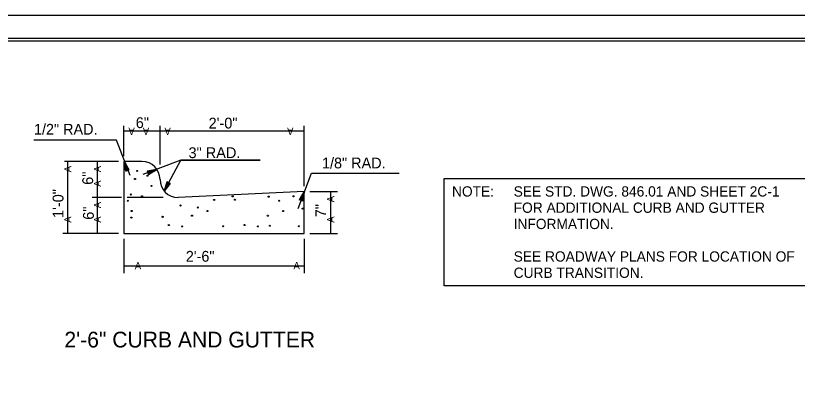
# Model space of a CAD drawing. Extents: x 1252282 to 1252460, y 733735 to 733845.
# Drawn here: x 1252344.6 to 1252421, y 733807 to 733844.5 of the extents above; entities that cross this region are included whole.
import ezdxf

# ---------------------------------------------------------------- set-up
doc = ezdxf.new("R2010")
doc.units = 0
for name, color, linetype in [('Default', 7, 'Continuous'), ('Old_Level_2', 7, 'Continuous'), ('Old_Level_23', 7, 'Continuous'), ('Old_Level_3', 7, 'Continuous'), ('Sheet Cutting Line CELL', 7, 'Continuous'), ('Sheet Plot Border Inside CELL', 7, 'Continuous'), ('Sheet Plot Border Outside CELL', 7, 'Continuous'), ('Sheet Typical CELL', 7, 'Continuous')]:
    doc.layers.add(name, color=color, linetype=linetype)

msp = doc.modelspace()

# ---------------------------------------------------------------- linework, layer by layer
at = {"layer": 'Default'}
msp.add_lwpolyline([(1252386.483, 733828.578), (1252426.564, 733828.578), (1252426.564, 733818.059), (1252386.483, 733818.059)], close=True, dxfattribs=at)
at = {"layer": 'Old_Level_2'}
for p, q in [((1252355.159, 733830.231), (1252355.653, 733829.406)), ((1252355.159, 733830.231), (1252355.34, 733829.287)), ((1252355.34, 733829.287), (1252355.653, 733829.406)), ((1252358.387, 733829.459), (1252357.448, 733829.278)), ((1252357.448, 733829.278), (1252357.567, 733828.961)), ((1252358.387, 733829.459), (1252357.567, 733828.961)), ((1252359.097, 733827.312), (1252359.397, 733828.22)), ((1252359.097, 733827.312), (1252359.688, 733828.061)), ((1252359.688, 733828.061), (1252359.397, 733828.22)), ((1252372.802, 733827.289), (1252372.317, 733826.474)), ((1252372.802, 733827.289), (1252372.621, 733826.346)), ((1252372.621, 733826.346), (1252372.317, 733826.474))]:
    msp.add_line(p, q, dxfattribs=at)
for points in [[(1252355.499, 733829.362), (1252355.172, 733830.2), (1252355.424, 733829.322), (1252355.172, 733830.209), (1252355.587, 733829.384), (1252355.177, 733830.2), (1252355.543, 733829.375), (1252355.177, 733830.2), (1252355.463, 733829.34), (1252355.177, 733830.2), (1252355.375, 733829.309), (1252355.177, 733830.2), (1252355.362, 733829.3), (1252355.177, 733830.2), (1252355.477, 733829.34), (1252355.177, 733830.178), (1252355.622, 733829.393), (1252355.181, 733830.187), (1252355.569, 733829.375), (1252355.208, 733830.125), (1252355.53, 733829.362), (1252355.181, 733830.187), (1252355.521, 733829.362), (1252355.181, 733830.178), (1252355.411, 733829.322), (1252355.186, 733830.169), (1252355.437, 733829.331), (1252355.181, 733830.169), (1252355.605, 733829.393), (1252355.177, 733830.187), (1252355.649, 733829.406), (1252355.181, 733830.169), (1252355.649, 733829.406), (1252355.186, 733830.187), (1252355.331, 733829.957), (1252355.203, 733830.169), (1252355.596, 733829.384), (1252355.181, 733830.169), (1252355.349, 733829.3), (1252355.181, 733830.147), (1252355.344, 733829.3), (1252355.172, 733830.209), (1252355.393, 733829.309), (1252355.203, 733830.156), (1252355.472, 733829.34), (1252355.186, 733830.169), (1252355.455, 733829.34), (1252355.203, 733830.147), (1252355.556, 733829.375), (1252355.181, 733830.187), (1252355.631, 733829.406), (1252355.181, 733830.187), (1252355.371, 733829.3), (1252355.181, 733830.187), (1252355.415, 733829.309), (1252355.181, 733830.169), (1252355.494, 733829.353), (1252355.181, 733830.169), (1252355.525, 733829.362), (1252355.181, 733830.178), (1252355.552, 733829.375), (1252355.181, 733830.178), (1252355.583, 733829.384), (1252355.177, 733830.187), (1252355.613, 733829.406), (1252355.181, 733830.187), (1252355.6, 733829.384), (1252355.181, 733830.187), (1252355.627, 733829.406), (1252355.181, 733830.178), (1252355.468, 733829.34), (1252355.177, 733830.2), (1252355.503, 733829.362), (1252355.177, 733830.2), (1252355.441, 733829.34), (1252355.177, 733830.187), (1252355.428, 733829.322), (1252355.181, 733830.169), (1252355.397, 733829.309), (1252355.177, 733830.187), (1252355.371, 733829.3), (1252355.212, 733830.028), (1252355.362, 733829.3), (1252355.265, 733829.807), (1252355.349, 733829.3), (1252355.296, 733829.746), (1252355.424, 733829.322), (1252355.309, 733829.701), (1252355.534, 733829.362), (1252355.283, 733829.944), (1252355.552, 733829.375), (1252355.305, 733829.869), (1252355.543, 733829.362), (1252355.336, 733829.785), (1252355.499, 733829.353), (1252355.349, 733829.71), (1252355.49, 733829.353), (1252355.283, 733829.975), (1252355.583, 733829.375), (1252355.344, 733829.851), (1252355.583, 733829.384)], [(1252357.518, 733829.111), (1252358.365, 733829.446), (1252357.487, 733829.194), (1252358.378, 733829.446), (1252357.554, 733829.022), (1252358.356, 733829.437), (1252357.532, 733829.075), (1252358.365, 733829.437), (1252357.505, 733829.15), (1252358.365, 733829.437), (1252357.465, 733829.234), (1252358.365, 733829.437), (1252357.461, 733829.247), (1252358.365, 733829.437), (1252357.505, 733829.141), (1252358.334, 733829.437), (1252357.558, 733828.983), (1252358.347, 733829.428), (1252357.54, 733829.044), (1252358.281, 733829.406), (1252357.527, 733829.089), (1252358.347, 733829.428), (1252357.518, 733829.097), (1252358.334, 733829.428), (1252357.487, 733829.203), (1252358.325, 733829.428), (1252357.492, 733829.172), (1252358.325, 733829.428), (1252357.558, 733829.014), (1252358.352, 733829.437), (1252357.567, 733828.969), (1252358.33, 733829.428), (1252357.567, 733828.969), (1252358.347, 733829.428), (1252358.122, 733829.287), (1252358.325, 733829.415), (1252357.554, 733829.022), (1252358.325, 733829.428), (1252357.461, 733829.269), (1252358.312, 733829.428), (1252357.457, 733829.269), (1252358.378, 733829.446), (1252357.479, 733829.225), (1252358.321, 733829.415), (1252357.505, 733829.141), (1252358.325, 733829.428), (1252357.501, 733829.164), (1252358.312, 733829.415), (1252357.54, 733829.058), (1252358.352, 733829.428), (1252357.567, 733828.983), (1252358.352, 733829.428), (1252357.461, 733829.234), (1252358.347, 733829.428), (1252357.479, 733829.203), (1252358.325, 733829.428), (1252357.509, 733829.119), (1252358.33, 733829.428), (1252357.527, 733829.089), (1252358.334, 733829.428), (1252357.54, 733829.058), (1252358.334, 733829.428), (1252357.554, 733829.036), (1252358.347, 733829.437), (1252357.562, 733829.005), (1252358.347, 733829.428), (1252357.554, 733829.014), (1252358.352, 733829.428), (1252357.562, 733828.983), (1252358.334, 733829.428), (1252357.505, 733829.15), (1252358.365, 733829.437), (1252357.518, 733829.111), (1252358.356, 733829.437), (1252357.501, 733829.172), (1252358.352, 733829.437), (1252357.487, 733829.181), (1252358.33, 733829.428), (1252357.479, 733829.216), (1252358.352, 733829.437), (1252357.461, 733829.234), (1252358.193, 733829.406), (1252357.457, 733829.256), (1252357.964, 733829.353), (1252357.457, 733829.269), (1252357.906, 733829.322), (1252357.487, 733829.194), (1252357.871, 733829.3), (1252357.532, 733829.075), (1252358.1, 733829.331), (1252357.532, 733829.058), (1252358.03, 733829.309), (1252357.527, 733829.075), (1252357.95, 733829.278), (1252357.509, 733829.111), (1252357.875, 733829.269), (1252357.509, 733829.128), (1252358.136, 733829.331), (1252357.54, 733829.036), (1252358.012, 733829.269), (1252357.554, 733829.022)], [(1252359.538, 733828.136), (1252359.106, 733827.329), (1252359.604, 733828.105), (1252359.106, 733827.329), (1252359.463, 733828.189), (1252359.115, 733827.342), (1252359.494, 733828.158), (1252359.106, 733827.329), (1252359.573, 733828.123), (1252359.115, 733827.329), (1252359.653, 733828.083), (1252359.106, 733827.329), (1252359.661, 733828.07), (1252359.106, 733827.342), (1252359.556, 733828.136), (1252359.119, 733827.364), (1252359.423, 733828.198), (1252359.119, 733827.364), (1252359.472, 733828.176), (1252359.154, 733827.417), (1252359.511, 733828.158), (1252359.119, 733827.364), (1252359.525, 733828.145), (1252359.128, 733827.364), (1252359.622, 733828.092), (1252359.128, 733827.373), (1252359.595, 733828.114), (1252359.141, 733827.373), (1252359.436, 733828.198), (1252359.119, 733827.351), (1252359.406, 733828.211), (1252359.128, 733827.373), (1252359.406, 733828.22), (1252359.115, 733827.364), (1252359.203, 733827.616), (1252359.128, 733827.382), (1252359.459, 733828.189), (1252359.141, 733827.373), (1252359.679, 733828.061), (1252359.145, 733827.373), (1252359.679, 733828.061), (1252359.106, 733827.329), (1252359.635, 733828.083), (1252359.141, 733827.382), (1252359.556, 733828.123), (1252359.141, 733827.373), (1252359.582, 733828.123), (1252359.141, 733827.395), (1252359.476, 733828.167), (1252359.115, 733827.351), (1252359.41, 733828.211), (1252359.115, 733827.351), (1252359.657, 733828.07), (1252359.119, 733827.364), (1252359.622, 733828.092), (1252359.128, 733827.373), (1252359.542, 733828.136), (1252359.128, 733827.373), (1252359.52, 733828.158), (1252359.128, 733827.364), (1252359.489, 733828.167), (1252359.128, 733827.364), (1252359.467, 733828.176), (1252359.128, 733827.351), (1252359.432, 733828.198), (1252359.119, 733827.364), (1252359.445, 733828.198), (1252359.115, 733827.351), (1252359.414, 733828.211), (1252359.128, 733827.364), (1252359.564, 733828.123), (1252359.106, 733827.329), (1252359.529, 733828.136), (1252359.115, 733827.342), (1252359.591, 733828.114), (1252359.115, 733827.342), (1252359.6, 733828.114), (1252359.128, 733827.373), (1252359.635, 733828.092), (1252359.119, 733827.351), (1252359.661, 733828.07), (1252359.212, 733827.488), (1252359.67, 733828.07), (1252359.353, 733827.669), (1252359.679, 733828.07), (1252359.37, 733827.735), (1252359.617, 733828.092), (1252359.397, 733827.775), (1252359.498, 733828.158), (1252359.234, 733827.585), (1252359.489, 733828.167), (1252359.282, 733827.66), (1252359.498, 733828.158), (1252359.317, 733827.735), (1252359.538, 733828.136), (1252359.366, 733827.797), (1252359.551, 733828.136), (1252359.212, 733827.563), (1252359.467, 733828.189), (1252359.264, 733827.691), (1252359.463, 733828.189)], [(1252372.462, 733826.421), (1252372.797, 733827.267), (1252372.542, 733826.377), (1252372.797, 733827.267), (1252372.378, 733826.443), (1252372.793, 733827.259), (1252372.422, 733826.43), (1252372.793, 733827.267), (1252372.506, 733826.399), (1252372.793, 733827.267), (1252372.586, 733826.368), (1252372.793, 733827.267), (1252372.608, 733826.359), (1252372.793, 733827.267), (1252372.484, 733826.412), (1252372.793, 733827.237), (1252372.348, 733826.452), (1252372.78, 733827.245), (1252372.396, 733826.443), (1252372.758, 733827.184), (1252372.431, 733826.421), (1252372.78, 733827.245), (1252372.449, 733826.421), (1252372.78, 733827.237), (1252372.555, 733826.377), (1252372.775, 733827.223), (1252372.528, 733826.39), (1252372.78, 733827.223), (1252372.356, 733826.452), (1252372.793, 733827.245), (1252372.321, 733826.474), (1252372.78, 733827.237), (1252372.321, 733826.474), (1252372.775, 733827.245), (1252372.639, 733827.012), (1252372.766, 733827.223), (1252372.37, 733826.443), (1252372.78, 733827.223), (1252372.612, 733826.359), (1252372.78, 733827.206), (1252372.616, 733826.359), (1252372.797, 733827.267), (1252372.572, 733826.377), (1252372.766, 733827.214), (1252372.489, 733826.412), (1252372.775, 733827.223), (1252372.511, 733826.399), (1252372.766, 733827.206), (1252372.409, 733826.443), (1252372.78, 733827.245), (1252372.33, 733826.474), (1252372.78, 733827.245), (1252372.59, 733826.359), (1252372.78, 733827.245), (1252372.546, 733826.377), (1252372.78, 733827.223), (1252372.475, 733826.412), (1252372.78, 733827.237), (1252372.44, 733826.421), (1252372.78, 733827.237), (1252372.414, 733826.43), (1252372.78, 733827.237), (1252372.383, 733826.443), (1252372.793, 733827.245), (1252372.352, 733826.465), (1252372.78, 733827.245), (1252372.361, 733826.443), (1252372.78, 733827.245), (1252372.334, 733826.465), (1252372.78, 733827.237), (1252372.493, 733826.412), (1252372.793, 733827.267), (1252372.458, 733826.421), (1252372.793, 733827.259), (1252372.519, 733826.399), (1252372.793, 733827.245), (1252372.537, 733826.377), (1252372.78, 733827.237), (1252372.568, 733826.377), (1252372.793, 733827.245), (1252372.59, 733826.359), (1252372.749, 733827.087), (1252372.608, 733826.359), (1252372.7, 733826.866), (1252372.612, 733826.359), (1252372.669, 733826.8), (1252372.542, 733826.377), (1252372.652, 733826.76), (1252372.427, 733826.421), (1252372.678, 733827.003), (1252372.414, 733826.43), (1252372.665, 733826.928), (1252372.422, 733826.421), (1252372.634, 733826.853), (1252372.462, 733826.412), (1252372.612, 733826.769), (1252372.48, 733826.412), (1252372.678, 733827.034), (1252372.383, 733826.443), (1252372.616, 733826.919), (1252372.383, 733826.443)]]:
    msp.add_lwpolyline(points, dxfattribs=at)
at = {"layer": 'Old_Level_23'}
for p, q in [((1252355.159, 733830.76), (1252355.159, 733833.714)), ((1252358.696, 733833.185), (1252355.159, 733833.185)), ((1252358.696, 733829.922), (1252358.696, 733833.714)), ((1252372.802, 733833.185), (1252358.696, 733833.185)), ((1252372.802, 733827.819), (1252372.802, 733833.714)), ((1252354.634, 733830.231), (1252349.361, 733830.231)), ((1252349.678, 733823.171), (1252349.678, 733830.231)), ((1252352.588, 733826.694), (1252352.588, 733830.231)), ((1252373.331, 733827.289), (1252376.065, 733827.289)), ((1252375.386, 733823.171), (1252375.386, 733827.289)), ((1252354.921, 733826.694), (1252352.055, 733826.694)), ((1252352.588, 733823.171), (1252352.588, 733826.694)), ((1252359, 733826.694), (1252355.472, 733826.694)), ((1252354.634, 733823.171), (1252349.198, 733823.171)), ((1252373.331, 733823.171), (1252376.065, 733823.171)), ((1252355.159, 733822.642), (1252355.159, 733819.308)), ((1252372.802, 733822.642), (1252372.802, 733819.308)), ((1252355.159, 733820.027), (1252372.802, 733820.027))]:
    msp.add_line(p, q, dxfattribs=at)
for points in [[(1252355.755, 733828.855), (1252354.44, 733832.316), (1252346.345, 733832.316)], [(1252359.097, 733827.312), (1252360.733, 733830.345), (1252368.489, 733830.345), (1252360.733, 733830.345), (1252357.011, 733828.939)], [(1252372.189, 733825.627), (1252373.498, 733829.089), (1252382.093, 733829.089)]]:
    msp.add_lwpolyline(points, dxfattribs=at)
at = {"layer": 'Old_Level_3'}
msp.add_lwpolyline([(1252356.927, 733830.231), (1252355.159, 733830.231), (1252355.159, 733823.171), (1252372.802, 733823.171), (1252372.802, 733827.289), (1252360.451, 733826.694)], dxfattribs=at)
for centre, radius in [((1252356.458, 733829.302), 0.0517), ((1252356.246, 733828.514), 0.0517), ((1252357.463, 733828.839), 0.0517), ((1252357.847, 733827.836), 0.0517), ((1252355.839, 733826.995), 0.0517), ((1252355.532, 733826.384), 0.0517), ((1252356.925, 733826.822), 0.0548), ((1252363.988, 733826.458), 0.0517), ((1252365.797, 733826.804), 0.0517), ((1252366.019, 733826.487), 0.0517), ((1252369.316, 733826.783), 0.0517), ((1252370.348, 733826.384), 0.0517), ((1252371.741, 733826.822), 0.0548), ((1252355.915, 733825.381), 0.0517), ((1252360.688, 733825.921), 0.0517), ((1252362.391, 733825.728), 0.0561), ((1252363.323, 733825.381), 0.0517), ((1252370.731, 733825.381), 0.0517), ((1252372.639, 733825.614), 0.0517), ((1252355.889, 733824.735), 0.0517), ((1252358.947, 733824.81), 0.0517), ((1252361.821, 733824.923), 0.0556), ((1252369.229, 733824.923), 0.0556), ((1252359.551, 733824.011), 0.0517), ((1252360.858, 733823.876), 0.0517), ((1252364.871, 733823.886), 0.0517), ((1252366.959, 733824.011), 0.0517), ((1252368.266, 733823.876), 0.0517), ((1252369.438, 733823.939), 0.0517), ((1252372.279, 733823.886), 0.0517)]:
    msp.add_circle(centre, radius, dxfattribs=at)
for centre, start, end in [((1252356.927, 733828.464), 0, 90), ((1252360.454, 733828.464), 180, 270)]:
    msp.add_arc(centre, 1.764, start, end, dxfattribs=at)
at = {"layer": 'Sheet Cutting Line CELL'}
msp.add_line((1252450.583, 733844.502), (1252282.183, 733844.502), dxfattribs=at)
at = {"layer": 'Sheet Plot Border Inside CELL'}
msp.add_lwpolyline([(1252450.133, 733842.257), (1252283.483, 733842.257), (1252283.483, 733736.747), (1252450.133, 733736.747)], close=True, dxfattribs=at)
at = {"layer": 'Sheet Plot Border Outside CELL'}
msp.add_lwpolyline([(1252450.583, 733844.502), (1252282.183, 733844.502), (1252282.183, 733734.502), (1252450.583, 733734.502)], close=True, dxfattribs=at)
at = {"layer": 'Sheet Typical CELL'}
msp.add_lwpolyline([(1252448.883, 733842.002), (1252298.883, 733842.002), (1252298.883, 733737.002), (1252448.883, 733737.002)], close=True, dxfattribs=at)

# ---------------------------------------------------------------- texts
at = {"layer": 'Default'}
for s, height, p in [('NOTE:', 1.0054, (1252387.248, 733826.795)), ('SEE STD. DWG. 846.01 AND SHEET 2C-1 ', 1.00537, (1252393.281, 733826.795)), ('FOR ADDITIONAL CURB AND GUTTER ', 1.00537, (1252393.281, 733825.203)), ('INFORMATION.', 1.00537, (1252393.281, 733823.612)), ('SEE ROADWAY PLANS FOR LOCATION OF ', 1.00537, (1252393.281, 733820.428)), ('CURB TRANSITION.', 1.00537, (1252393.281, 733818.836))]:
    msp.add_text(s, height=height, dxfattribs=at).set_placement(p)
at = {"layer": 'Old_Level_23'}
for s, height, p in [('6"', 1.0603, (1252356.319, 733833.494)), ('1/2" RAD.', 1.0541, (1252346.362, 733832.854)), ('2\'-0"', 1.0603, (1252363.445, 733833.45)), ('3" RAD.', 1.0603, (1252361.478, 733830.557)), ('1/8" RAD.', 1.0541, (1252374.535, 733829.552)), ('2\'-6"', 1.0541, (1252361.213, 733820.419)), ('A', 0.698, (1252356.222, 733819.679)), ('A', 0.698, (1252371.743, 733819.679)), ('2\'-6" CURB AND GUTTER', 1.54332, (1252349.339, 733812.024))]:
    msp.add_text(s, height=height, dxfattribs=at).set_placement(p)
for s, height, rotation, p in [('A', 0.698, 180, (1252356.222, 733833.533)), ('A', 0.698, 180, (1252357.633, 733833.533)), ('A', 0.698, 180, (1252359.75, 733833.533)), ('A', 0.698, 180, (1252371.743, 733833.533)), ('A', 0.698, 90, (1252350.022, 733829.172)), ('A', 0.698, 90, (1252352.928, 733829.172)), ('6"', 1.0603, 90, (1252352.148, 733827.946)), ('A', 0.698, 90, (1252352.928, 733827.752)), ('1\'-0"', 1.0603, 90, (1252349.25, 733824.701)), ('A', 0.698, 90, (1252352.928, 733825.649)), ('A', 0.698, 90, (1252375.734, 733826.231)), ('6"', 1.0603, 90, (1252352.218, 733824.525)), ('7"', 1.0541, 90, (1252374.94, 733824.772)), ('A', 0.698, 90, (1252350.022, 733824.229)), ('A', 0.698, 90, (1252352.928, 733824.229)), ('A', 0.698, 90, (1252375.734, 733824.229))]:
    msp.add_text(s, height=height, rotation=rotation, dxfattribs=at).set_placement(p)

doc.saveas('drawing.dxf')
